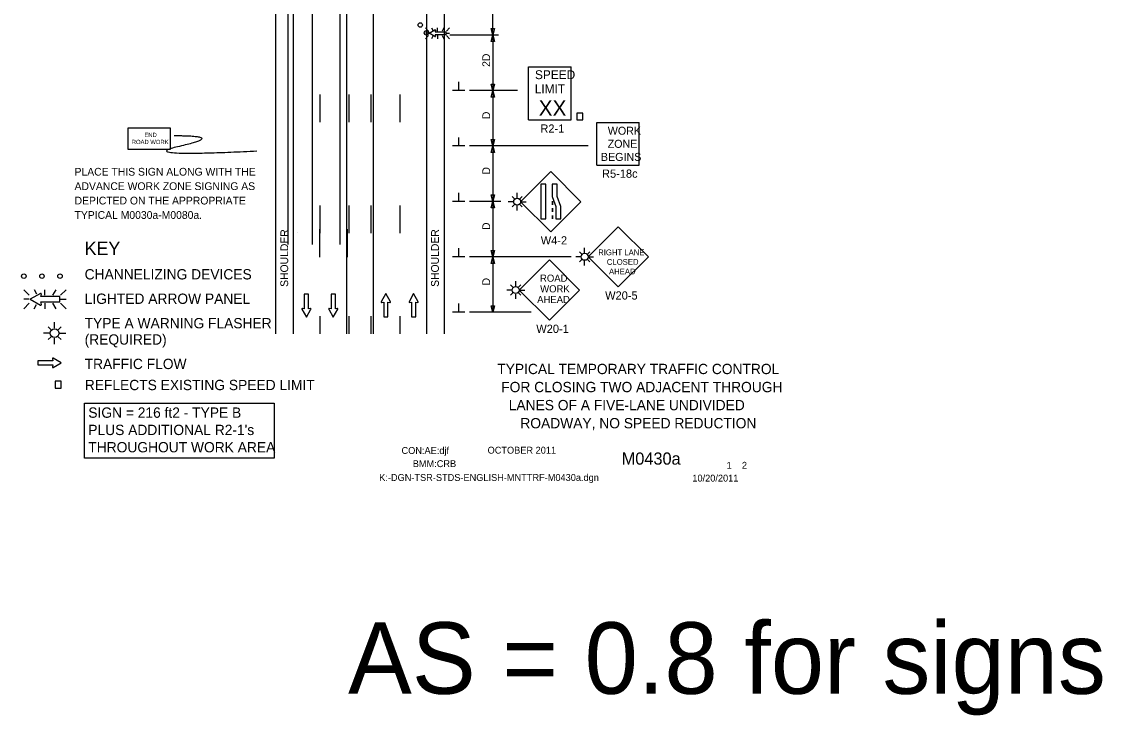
# Model space of a CAD drawing. Extents: x 16748 to 18475, y 7008 to 8262.
# Drawn here: x 16748 to 17723, y 7008 to 7634 of the extents above; entities that cross this region are included whole.
import ezdxf

# ---------------------------------------------------------------- set-up
doc = ezdxf.new("R2010")
doc.units = 0
for name, color, linetype in [('ALI_LEGAL_EX', 7, 'Continuous'), ('BORDER', 7, 'Continuous'), ('BORDER_SIGNAL_WO', 7, 'Continuous'), ('MT_SCRATCH_LEVEL_E', 7, 'Continuous'), ('PAVT_EDGE_EX', 7, 'Continuous'), ('TRAFFIC_SIGNS_PR', 7, 'Continuous'), ('TYPICAL_TEXT_DIMEN_EX', 7, 'Continuous'), ('TYPICAL_TEXT_DIMEN_PR', 7, 'Continuous')]:
    doc.layers.add(name, color=color, linetype=linetype)

msp = doc.modelspace()

# ---------------------------------------------------------------- linework, layer by layer
at = {"layer": 'ALI_LEGAL_EX'}
for points in [[(17017.08, 7568.47), (17017.08, 7543.47)], [(17043.08, 7568.47), (17043.08, 7543.47)], [(17063.08, 7568.47), (17063.08, 7543.47)], [(17089.08, 7568.47), (17089.08, 7543.47)], [(17017.08, 7468.47), (17017.08, 7443.47)], [(17043.08, 7468.47), (17043.08, 7443.47)], [(17063.08, 7468.47), (17063.08, 7443.47)], [(17089.08, 7468.47), (17089.08, 7443.47)], [(17017.08, 7368.47), (17017.08, 7352.54)], [(17043.08, 7368.47), (17043.08, 7352.54)], [(17063.08, 7368.47), (17063.08, 7352.54)], [(17089.08, 7368.47), (17089.08, 7352.54)]]:
    msp.add_lwpolyline(points, dxfattribs=at)
at = {"layer": 'BORDER'}
msp.add_line((16996.79, 7443.92), (16996.79, 7443.92), dxfattribs=at)
at = {"layer": 'MT_SCRATCH_LEVEL_E'}
for p, q in [((17006.75, 7388.42), (17003.01, 7388.42)), ((17003.01, 7388.42), (17003.01, 7375.16)), ((17006.75, 7388.42), (17003.01, 7388.42)), ((17003.01, 7388.42), (17003.01, 7375.16)), ((17006.75, 7375.16), (17006.75, 7388.42)), ((17006.75, 7375.16), (17006.75, 7388.42)), ((17031.01, 7388.42), (17027.26, 7388.42)), ((17027.26, 7388.42), (17027.26, 7375.16)), ((17031.01, 7388.42), (17027.26, 7388.42)), ((17027.26, 7388.42), (17027.26, 7375.16)), ((17031.01, 7375.16), (17031.01, 7388.42)), ((17031.01, 7375.16), (17031.01, 7388.42)), ((17076.52, 7388.88), (17072.41, 7381.64)), ((17076.52, 7388.88), (17072.41, 7381.64)), ((17080.67, 7381.64), (17076.52, 7388.88)), ((17080.67, 7381.64), (17076.52, 7388.88)), ((17101.61, 7388.88), (17097.5, 7381.64)), ((17101.61, 7388.88), (17097.5, 7381.64)), ((17105.75, 7381.64), (17101.61, 7388.88)), ((17105.75, 7381.64), (17101.61, 7388.88)), ((17072.89, 7380.95), (17074.67, 7381.27)), ((17072.89, 7380.95), (17074.67, 7381.27)), ((17074.67, 7381.27), (17074.67, 7368.01)), ((17074.67, 7381.27), (17074.67, 7368.01)), ((17078.41, 7368.01), (17078.41, 7381.27)), ((17078.41, 7381.27), (17080.19, 7380.95)), ((17078.41, 7368.01), (17078.41, 7381.27)), ((17078.41, 7381.27), (17080.19, 7380.95)), ((17097.98, 7380.95), (17099.76, 7381.27)), ((17097.98, 7380.95), (17099.76, 7381.27)), ((17099.76, 7381.27), (17099.76, 7368.01)), ((17099.76, 7381.27), (17099.76, 7368.01)), ((17103.5, 7368.01), (17103.5, 7381.27)), ((17103.5, 7381.27), (17105.28, 7380.95)), ((17103.5, 7368.01), (17103.5, 7381.27)), ((17103.5, 7381.27), (17105.28, 7380.95)), ((17000.75, 7374.79), (17004.9, 7367.55)), ((17000.75, 7374.79), (17004.9, 7367.55)), ((17003.01, 7375.16), (17001.23, 7375.48)), ((17003.01, 7375.16), (17001.23, 7375.48)), ((17004.9, 7367.55), (17009.01, 7374.79)), ((17004.9, 7367.55), (17009.01, 7374.79)), ((17008.53, 7375.48), (17006.75, 7375.16)), ((17008.53, 7375.48), (17006.75, 7375.16)), ((17025.01, 7374.79), (17029.15, 7367.55)), ((17025.01, 7374.79), (17029.15, 7367.55)), ((17027.26, 7375.16), (17025.49, 7375.48)), ((17027.26, 7375.16), (17025.49, 7375.48)), ((17029.15, 7367.55), (17033.27, 7374.79)), ((17029.15, 7367.55), (17033.27, 7374.79)), ((17032.78, 7375.48), (17031.01, 7375.16)), ((17032.78, 7375.48), (17031.01, 7375.16)), ((17074.67, 7368.01), (17078.41, 7368.01)), ((17074.67, 7368.01), (17078.41, 7368.01)), ((17099.76, 7368.01), (17103.5, 7368.01)), ((17099.76, 7368.01), (17103.5, 7368.01)), ((16775.82, 7330.11), (16776.13, 7328.33)), ((16775.82, 7330.11), (16776.13, 7328.33)), ((16783.74, 7326.48), (16776.5, 7330.59)), ((16783.74, 7326.48), (16776.5, 7330.59)), ((16776.13, 7328.33), (16762.87, 7328.33)), ((16762.87, 7328.33), (16762.87, 7324.59)), ((16776.13, 7328.33), (16762.87, 7328.33)), ((16762.87, 7328.33), (16762.87, 7324.59)), ((16762.87, 7324.59), (16776.13, 7324.59)), ((16762.87, 7324.59), (16776.13, 7324.59)), ((16776.13, 7324.59), (16775.82, 7322.82)), ((16776.13, 7324.59), (16775.82, 7322.82)), ((16776.5, 7322.34), (16783.74, 7326.48)), ((16776.5, 7322.34), (16783.74, 7326.48))]:
    msp.add_line(p, q, dxfattribs=at)
for centre, start, end in [((17072.81, 7381.41), 150.42484, 279.96381), ((17072.81, 7381.41), 150.42484, 279.96381), ((17080.26, 7381.42), 260.03619, 29.77312), ((17080.26, 7381.42), 260.03619, 29.77312), ((17097.9, 7381.41), 150.42484, 279.96381), ((17097.9, 7381.41), 150.42484, 279.96381), ((17105.34, 7381.42), 260.03619, 29.77312), ((17105.34, 7381.42), 260.03619, 29.77312), ((17001.16, 7375.02), 80.03619, 209.77312), ((17001.16, 7375.02), 80.03619, 209.77312), ((17008.6, 7375.02), 330.42484, 99.96381), ((17008.6, 7375.02), 330.42484, 99.96381), ((17025.42, 7375.02), 80.03619, 209.77312), ((17025.42, 7375.02), 80.03619, 209.77312), ((17032.86, 7375.02), 330.42484, 99.96381), ((17032.86, 7375.02), 330.42484, 99.96381), ((16776.28, 7330.19), 60.42484, 189.96381), ((16776.28, 7330.19), 60.42484, 189.96381), ((16776.28, 7322.75), 170.03619, 299.77312), ((16776.28, 7322.75), 170.03619, 299.77312)]:
    msp.add_arc(centre, 0.463, start, end, dxfattribs=at)
at = {"layer": 'PAVT_EDGE_EX'}
for p, q in [((16988.15, 8262.34), (16988.15, 7433.15)), ((17010.15, 8262.34), (17010.15, 7433.15)), ((17035.15, 8262.34), (17035.15, 7433.15)), ((16977.08, 8185.96), (16977.08, 7352.54)), ((16993.08, 8185.96), (16993.08, 7352.54)), ((17041.08, 8185.96), (17041.08, 7352.54)), ((17113.08, 8185.96), (17113.08, 7352.54)), ((17129.08, 8185.96), (17129.08, 7352.54)), ((17065.08, 7708), (17065.08, 7352.54))]:
    msp.add_line(p, q, dxfattribs=at)
for points in [[(17017.08, 7421.93), (17017.08, 7446.93)], [(17042.08, 7421.93), (17042.08, 7446.93)]]:
    msp.add_lwpolyline(points, dxfattribs=at)
at = {"layer": 'TRAFFIC_SIGNS_PR'}
for p, q in [((17112.21, 7628.57), (17115.03, 7625.76)), ((17115.03, 7623.72), (17112.21, 7623.72)), ((17112.21, 7618.87), (17115.03, 7621.69)), ((17117.65, 7628.58), (17118.85, 7626.48)), ((17118.93, 7621.06), (17117.67, 7618.87)), ((17123.12, 7625.76), (17123.12, 7628.58)), ((17123.12, 7621.69), (17123.12, 7618.87)), ((17127.25, 7621.69), (17128.88, 7618.87)), ((17128.9, 7628.58), (17127.28, 7625.76)), ((17131.2, 7625.76), (17134.02, 7628.58)), ((17131.2, 7623.72), (17134.02, 7623.72)), ((17131.2, 7621.69), (17134.02, 7618.87)), ((17205.24, 7593.52), (17243.64, 7593.52)), ((17205.24, 7545.52), (17205.24, 7593.52)), ((17243.64, 7545.52), (17243.64, 7593.52)), ((17205.24, 7545.52), (17243.64, 7545.52)), ((17266.66, 7504.86), (17266.66, 7543.26)), ((17266.66, 7543.26), (17305.06, 7543.26)), ((17305.06, 7504.86), (17305.06, 7543.26)), ((17266.66, 7504.86), (17305.06, 7504.86)), ((17225.26, 7498.97), (17198.11, 7471.82)), ((17252.42, 7471.82), (17225.26, 7498.97)), ((17192.44, 7474.33), (17190.34, 7476.44)), ((17194.96, 7475.38), (17194.96, 7479.88)), ((17197.47, 7474.33), (17199.58, 7476.44)), ((17191.8, 7471.82), (17186.97, 7471.82)), ((17192.44, 7469.31), (17190.34, 7467.2)), ((17194.96, 7463.85), (17194.96, 7468.27)), ((17197.47, 7469.31), (17199.58, 7467.2)), ((17198.11, 7471.82), (17202.99, 7471.82)), ((17198.11, 7471.82), (17225.26, 7444.67)), ((17225.26, 7444.67), (17252.42, 7471.82)), ((17226.5, 7472.31), (17226.5, 7469.11)), ((17226.5, 7465.91), (17226.5, 7462.71)), ((17226.9, 7472.31), (17226.9, 7469.11)), ((17226.9, 7465.91), (17226.9, 7462.71)), ((17226.5, 7459.51), (17226.5, 7456.31)), ((17226.9, 7459.51), (17226.9, 7456.31)), ((17286.11, 7449.26), (17258.95, 7422.11)), ((17313.26, 7422.11), (17286.11, 7449.26)), ((17253.29, 7424.62), (17251.18, 7426.73)), ((17255.8, 7425.67), (17255.8, 7430.17)), ((17258.31, 7424.62), (17260.42, 7426.73)), ((17224.04, 7419.28), (17196.86, 7392.09)), ((17251.23, 7392.09), (17224.04, 7419.28)), ((17252.65, 7422.11), (17247.81, 7422.11)), ((17253.29, 7419.6), (17251.18, 7417.49)), ((17255.8, 7414.15), (17255.8, 7418.56)), ((17258.31, 7419.6), (17260.42, 7417.49)), ((17258.95, 7422.11), (17263.84, 7422.11)), ((17258.95, 7422.11), (17286.11, 7394.96)), ((17286.11, 7394.96), (17313.26, 7422.11)), ((17191.19, 7394.61), (17189.08, 7396.71)), ((17193.7, 7395.65), (17193.7, 7400.15)), ((17196.21, 7394.61), (17198.32, 7396.71)), ((16750.04, 7392.3), (16754.97, 7387.37)), ((16761.8, 7388.48), (16759.59, 7392.31)), ((16769.12, 7387.37), (16769.12, 7392.31)), ((16776.36, 7387.37), (16779.21, 7392.31)), ((16783.27, 7387.37), (16788.21, 7392.31)), ((17190.55, 7392.09), (17185.71, 7392.09)), ((17191.19, 7389.58), (17189.08, 7387.47)), ((17193.7, 7384.13), (17193.7, 7388.54)), ((17196.21, 7389.58), (17198.32, 7387.47)), ((17196.85, 7392.09), (17201.74, 7392.09)), ((17196.86, 7392.09), (17224.04, 7364.91)), ((17224.04, 7364.91), (17251.23, 7392.09)), ((16754.97, 7383.81), (16750.04, 7383.81)), ((16750.04, 7375.33), (16754.97, 7380.26)), ((16759.55, 7375.32), (16761.66, 7378.99)), ((16769.12, 7380.26), (16769.12, 7375.32)), ((16779.25, 7375.32), (16776.4, 7380.26)), ((16783.27, 7383.81), (16788.21, 7383.81)), ((16783.27, 7380.26), (16788.21, 7375.32)), ((16774.75, 7356.34), (16772.12, 7358.97)), ((16777.89, 7357.64), (16777.89, 7363.26)), ((16781.03, 7356.34), (16783.66, 7358.97)), ((16773.95, 7353.2), (16767.92, 7353.2)), ((16774.75, 7350.06), (16772.12, 7347.43)), ((16777.89, 7343.25), (16777.89, 7348.76)), ((16781.03, 7350.06), (16783.66, 7347.43)), ((16781.83, 7353.2), (16787.92, 7353.2))]:
    msp.add_line(p, q, dxfattribs=at)
for points in [[(17120.79, 7620.71), (17115.48, 7623.72), (17120.79, 7626.77)], [(17121.29, 7626.41), (17121.06, 7625.11), (17130.78, 7625.11), (17130.78, 7622.37), (17121.06, 7622.37), (17121.29, 7621.06)], [(16765.05, 7389.09), (16755.76, 7383.81), (16765.05, 7378.49)], [(16765.92, 7379.12), (16765.52, 7381.39), (16782.54, 7381.39), (16782.54, 7386.19), (16765.52, 7386.19), (16765.93, 7388.47)]]:
    msp.add_lwpolyline(points, dxfattribs=at)
for points in [[(17248.66, 7545.52), (17254.25, 7545.52), (17254.25, 7551.69), (17248.66, 7551.69)], [(16843.83, 7519.07), (16882.23, 7519.07), (16882.23, 7538.27), (16843.83, 7538.27)], [(17216.37, 7487.56), (17216.37, 7456.31), (17220.86, 7456.31), (17220.86, 7487.56)], [(17226.5, 7487.56), (17226.5, 7476.38), (17229.85, 7467.49), (17229.85, 7456.31), (17234.34, 7456.31), (17234.34, 7467.49), (17231, 7476.38), (17231, 7487.56)], [(16778.28, 7303.68), (16783.88, 7303.68), (16783.88, 7309.85), (16778.28, 7309.85)]]:
    msp.add_lwpolyline(points, close=True, dxfattribs=at)
for centre, radius in [((17107.6, 7631.22), 2), ((17113.09, 7624.09), 2), ((17194.96, 7471.82), 3.15), ((17255.8, 7422.11), 3.15), ((16750.12, 7404.64), 2), ((16766.42, 7404.64), 2), ((16782.72, 7404.64), 2), ((17193.7, 7392.09), 3.15), ((16777.89, 7353.2), 3.94)]:
    msp.add_circle(centre, radius, dxfattribs=at)
for centre, radius, start, end in [((17120.95, 7626.47), 0.341, 350.04067, 118.51671), ((17120.95, 7621.01), 0.341, 241.10835, 9.26922), ((16765.34, 7388.57), 0.598, 350.73078, 118.89165), ((16765.34, 7379.02), 0.597, 241.48329, 9.95933)]:
    msp.add_arc(centre, radius, start, end, dxfattribs=at)
msp.add_open_spline([(16885.82, 7531.45), (16933.06, 7531.45), (16848.04, 7512.11), (16960.33, 7517.6)], degree=2, dxfattribs=at)
at = {"layer": 'TYPICAL_TEXT_DIMEN_EX'}
msp.add_lwpolyline([(16804.92, 7290.05), (16975.93, 7290.05), (16975.93, 7240.37), (16804.92, 7240.37)], close=True, dxfattribs=at)
at = {"layer": 'TYPICAL_TEXT_DIMEN_PR'}
for p, q in [((17173.08, 7622.09), (17173.08, 7652.61)), ((17178.08, 7622.09), (17134.1, 7622.09)), ((17173.08, 7622.09), (17171.51, 7627.95)), ((17171.51, 7627.95), (17173.08, 7627.95)), ((17171.51, 7616.23), (17173.08, 7622.09)), ((17173.08, 7627.95), (17174.65, 7627.95)), ((17174.65, 7627.95), (17173.08, 7622.09)), ((17173.08, 7622.09), (17173.08, 7572.09)), ((17173.08, 7622.09), (17174.65, 7616.23)), ((17173.08, 7616.23), (17171.51, 7616.23)), ((17174.65, 7616.23), (17173.08, 7616.23)), ((17147.83, 7572.09), (17136.58, 7572.09)), ((17142.21, 7572.09), (17142.21, 7579.88)), ((17195.14, 7572.09), (17152.08, 7572.09)), ((17173.08, 7572.09), (17171.51, 7577.95)), ((17171.51, 7577.95), (17173.08, 7577.95)), ((17171.51, 7566.23), (17173.08, 7572.09)), ((17173.08, 7577.95), (17174.65, 7577.95)), ((17174.65, 7577.95), (17173.08, 7572.09)), ((17173.08, 7572.09), (17174.65, 7566.23)), ((17173.08, 7572.09), (17173.08, 7522.09)), ((17173.08, 7566.23), (17171.51, 7566.23)), ((17174.65, 7566.23), (17173.08, 7566.23)), ((17142.21, 7522.09), (17142.21, 7529.88)), ((17173.08, 7522.09), (17171.51, 7527.95)), ((17171.51, 7527.95), (17173.08, 7527.95)), ((17173.08, 7527.95), (17174.65, 7527.95)), ((17174.65, 7527.95), (17173.08, 7522.09)), ((17147.83, 7522.09), (17136.58, 7522.09)), ((17258.94, 7522.09), (17152.08, 7522.09)), ((17171.51, 7516.23), (17173.08, 7522.09)), ((17173.08, 7516.23), (17171.51, 7516.23)), ((17173.08, 7522.09), (17174.65, 7516.23)), ((17173.08, 7522.09), (17173.08, 7472.09)), ((17174.65, 7516.23), (17173.08, 7516.23)), ((17142.21, 7472.09), (17142.21, 7479.88)), ((17173.08, 7472.09), (17171.51, 7477.95)), ((17171.51, 7477.95), (17173.08, 7477.95)), ((17173.08, 7477.95), (17174.65, 7477.95)), ((17174.65, 7477.95), (17173.08, 7472.09)), ((17147.83, 7472.09), (17136.58, 7472.09)), ((17180.34, 7472.09), (17152.08, 7472.09)), ((17171.51, 7466.23), (17173.08, 7472.09)), ((17173.08, 7466.23), (17171.51, 7466.23)), ((17173.08, 7472.09), (17174.65, 7466.23)), ((17173.08, 7472.09), (17173.08, 7422.09)), ((17174.65, 7466.23), (17173.08, 7466.23)), ((17142.21, 7422.09), (17142.21, 7429.88)), ((17173.08, 7422.09), (17171.51, 7427.95)), ((17171.51, 7427.95), (17173.08, 7427.95)), ((17173.08, 7427.95), (17174.65, 7427.95)), ((17174.65, 7427.95), (17173.08, 7422.09)), ((17147.83, 7422.09), (17136.58, 7422.09)), ((17243.56, 7422.09), (17152.08, 7422.09)), ((17171.51, 7416.23), (17173.08, 7422.09)), ((17173.08, 7416.23), (17171.51, 7416.23)), ((17173.08, 7422.09), (17174.65, 7416.23)), ((17173.08, 7422.09), (17173.08, 7372.09)), ((17174.65, 7416.23), (17173.08, 7416.23)), ((17142.21, 7372.09), (17142.21, 7379.88)), ((17173.08, 7372.09), (17171.51, 7377.95)), ((17171.51, 7377.95), (17173.08, 7377.95)), ((17173.08, 7377.95), (17174.65, 7377.95)), ((17174.65, 7377.95), (17173.08, 7372.09)), ((17147.83, 7372.09), (17136.58, 7372.09)), ((17207.67, 7372.09), (17152.08, 7372.09))]:
    msp.add_line(p, q, dxfattribs=at)

# ---------------------------------------------------------------- texts
at = {"layer": 'BORDER_SIGNAL_WO'}
for s, height, p in [('TYPICAL TEMPORARY TRAFFIC CONTROL', 9.3, (17177.02, 7316.3)), ('FOR CLOSING TWO ADJACENT THROUGH', 9.3, (17180.6, 7300)), ('LANES OF A FIVE-LANE UNDIVIDED', 9.3, (17187.36, 7283.7)), ('ROADWAY, NO SPEED REDUCTION', 9.3, (17197.83, 7267.4)), ('CON:AE:djf', 6.2, (17090.69, 7244.31)), ('    OCTOBER 2011    ', 6.2, (17159.08, 7244.59)), ('    M0430a   ', 11, (17272.86, 7234.63)), ('BMM:CRB   ', 6.2, (17100.81, 7232.42)), (' 1    2 ', 6.2, (17381.45, 7230.95)), ('K:-DGN-TSR-STDS-ENGLISH-MNTTRF-M0430a.dgn        ', 6.2, (17070.55, 7219.96)), ('10/20/2011    ', 6.2, (17352.93, 7219.38)), ('AS = 0.8 for signs', 64.512, (17042.45, 7027.94))]:
    msp.add_text(s, height=height, dxfattribs=at).set_placement(p)
at = {"layer": 'TRAFFIC_SIGNS_PR'}
for s, height, p in [('SPEED', 8, (17211.01, 7582.38)), ('LIMIT', 8, (17210.84, 7569.58)), ('XX', 14.031, (17214.35, 7549.28)), ('END', 3.831, (16858.83, 7530.2)), ('R2-1', 7.44, (17215.91, 7534.08)), ('WORK', 7.217, (17276.66, 7532.23)), ('ROAD WORK', 3.831, (16847.44, 7523.81)), ('ZONE', 7.217, (17276.54, 7520.42)), ('BEGINS', 7.217, (17270.47, 7508.61)), ('PLACE THIS SIGN ALONG WITH THE', 7, (16795.86, 7495.33)), ('R5-18c', 7.44, (17271.47, 7493.42)), ('ADVANCE WORK ZONE SIGNING AS', 7, (16795.86, 7482.33)), ('DEPICTED ON THE APPROPRIATE', 7, (16795.86, 7469.33)), ('TYPICAL M0030a-M0080a.', 7, (16795.86, 7456.33)), ('W4-2', 7.44, (17216.22, 7433.23)), ('RIGHT LANE', 5.2, (17268.03, 7423.51)), ('CLOSED', 5.2, (17275.82, 7414.91)), ('AHEAD', 5.2, (17277.77, 7406.31)), ('ROAD', 6.408, (17215.57, 7399.64)), ('WORK', 6.408, (17215.68, 7390.03)), ('W20-5', 7.44, (17274.28, 7383.52)), ('AHEAD', 6.408, (17212.99, 7380.41)), ('W20-1', 7.449, (17212.2, 7353.45))]:
    msp.add_text(s, height=height, dxfattribs=at).set_placement(p)
at = {"layer": 'TYPICAL_TEXT_DIMEN_EX'}
for s, height, p in [('KEY', 12, (16804.96, 7423.75)), ('CHANNELIZING DEVICES', 9.3, (16804.96, 7401.7)), ('LIGHTED ARROW PANEL', 9.3, (16804.96, 7379.65)), ('TYPE A WARNING FLASHER', 9.3, (16804.96, 7357.6)), ('(REQUIRED)', 9.3, (16804.96, 7342.9)), ('TRAFFIC FLOW', 9.3, (16804.96, 7320.85)), ('REFLECTS EXISTING SPEED LIMIT', 9.3, (16805.09, 7301.84)), ('SIGN = 216 ft2 - TYPE B', 9.3, (16808.26, 7276.93)), ("PLUS ADDITIONAL R2-1's", 9.3, (16808.26, 7261.33)), ('THROUGHOUT WORK AREA', 9.3, (16808.26, 7245.73))]:
    msp.add_text(s, height=height, dxfattribs=at).set_placement(p)
at = {"layer": 'TYPICAL_TEXT_DIMEN_PR'}
for s, p in [('2D', (17170.52, 7593.44)), ('D', (17170.52, 7546.31)), ('D', (17170.52, 7496.31)), ('SHOULDER', (16988.46, 7394.99)), ('SHOULDER', (17124.36, 7394.99)), ('D', (17170.52, 7446.31)), ('D', (17170.52, 7396.31))]:
    msp.add_text(s, height=7, rotation=90, dxfattribs=at).set_placement(p)

doc.saveas('drawing.dxf')
